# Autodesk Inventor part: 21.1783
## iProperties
Created: 2007-04
Part Number: 21.1783
Document SubType Name: Modeling
Designer: Andy Moles
Material: Aluminum-6061
Mass: 142.779 g
Surface Area: 149.136 cm^2
Volume: 52.6861 cm^3
Density: 2.71 g/cm^3
Author: Andy Moles
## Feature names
1. Extrusion1
2. Extrusion2
3. Extrusion3
4. Hole1
5. Hole2
6. Extrusion4
7. Extrusion5
